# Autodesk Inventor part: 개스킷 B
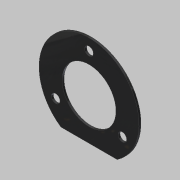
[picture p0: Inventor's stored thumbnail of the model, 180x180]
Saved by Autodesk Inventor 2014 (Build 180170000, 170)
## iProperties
Created: 2020-04
Part Number: 개스킷 B
Material: 고무
Document SubType Name: Modeling
Designer: mduedu
Density: 0.93 g/cm^3
Appearance: 고무 - 검은색 - 버전 1.1
Mass: 1.27493 g
Surface Area: 30.3371 cm^2
Volume: 1.37089 cm^3
Author: mduedu
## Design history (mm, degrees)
sketch "스케치1"
  geometry: C1 r 26 at (0, 0); 1 further point
  constraints: 1 centre point, 1 coincident
  dimensions: "d0" = 52 diameter of C1
extrude "돌출1" new body sketch "스케치1" distance "d1" = 1; taper "d2" = 0 deg
sketch "스케치2"
  geometry: L1 (-14.62, -21.5)-(14.62, -21.5); A1 r 26 centre (0, 0) between (-14.62, -21.5) and (14.62, -21.5) reference; 1 further point
  constraints: 2 end point, 2 point on circle, 1 horizontal
  dimensions: "d3" = 21.5 distance from line of L1 point (0, 0)
extrude "돌출2" cut sketch "스케치2" stored distance "d4" = 1; taper "d5" = 0 deg
sketch "스케치3" dims "d6" = 40
  geometry: 3 further points
  constraints: 2 vertical alignment, 1 coincident, 2 other
hole "구멍1" sketch "스케치3" at (0, 20) diameter "d7" = 4.5; stored, may be unused: countersink angle "d11" = 90 deg, drill point angle "d13" = 118 deg; dims "d8" = 6, "d9" = 4, "d10" = 2, "d12" = 8
sketch "스케치4"
  geometry: C1 r 14 at (0, 0); 1 further point
  constraints: 1 centre point, 1 coincident
  dimensions: "d17" = 28 diameter of C1
extrude "돌출3" cut sketch "스케치4" stored distance "d18" = 1; taper "d19" = 0 deg
node "솔리드1"
pattern_circular "원형 패턴1" dims angle "d15" = 360 deg
node "투영된 루프1"
